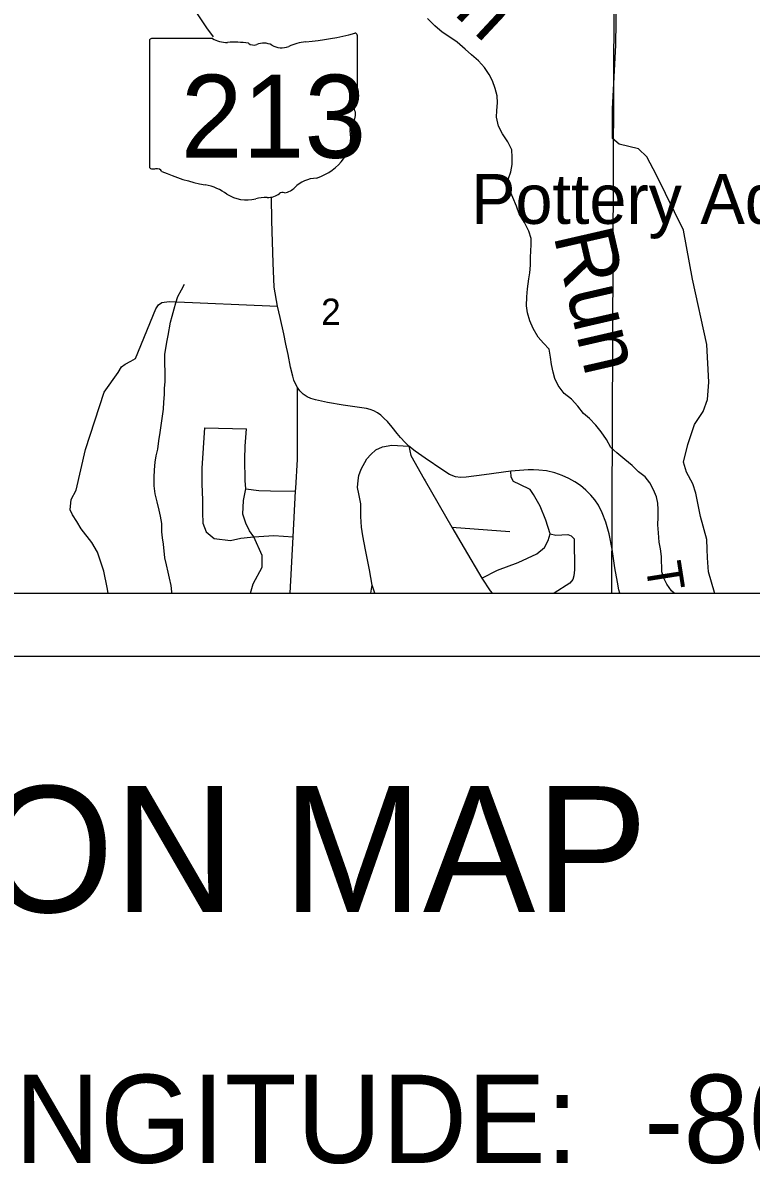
# Model space of a CAD drawing. Extents: x 0 to 34, y 0 to 22.
# Drawn here: x 5.456 to 6.612, y 13.194 to 15.005 of the extents above; entities that cross this region are included whole.
import ezdxf

# ---------------------------------------------------------------- set-up
doc = ezdxf.new("R2010")
doc.units = 0
for name, color, linetype in [('Default', 7, 'Continuous'), ('GM_X_Minor_River', 7, 'Continuous'), ('GM_X_Minor_River_Text', 7, 'Continuous'), ('GM_X_Section_Text', 7, 'Continuous'), ('GM_X_State_Location', 7, 'Continuous'), ('GM_X_State_Route', 7, 'Continuous'), ('GM_X_State_Shield', 7, 'Continuous'), ('GM_X_Township_Road', 7, 'Continuous'), ('GM_X_Township_Road_Text', 7, 'Continuous'), ('GM_X_Unincorporated_Text', 7, 'Continuous'), ('SH_Cut_Line', 7, 'Continuous'), ('SH_Data', 7, 'Continuous'), ('SH_Text', 7, 'Continuous')]:
    doc.layers.add(name, color=color, linetype=linetype)

msp = doc.modelspace()

# ---------------------------------------------------------------- linework, layer by layer
at = {"layer": 'Default'}
for p, q in [((6.3909, 14.1), (6.3944, 15.0386)), ((2.1, 14.1), (6.7017, 14.1)), ((5.3878, 14.1), (6.3909, 14.1))]:
    msp.add_line(p, q, dxfattribs=at)
at = {"layer": 'GM_X_Minor_River'}
for p, q in [((6.11, 15.0003), (6.0986, 15.0121)), ((6.1218, 14.9901), (6.11, 15.0003)), ((6.1338, 14.9821), (6.1218, 14.9901)), ((6.1455, 14.9744), (6.1338, 14.9821)), ((6.1583, 14.9634), (6.1455, 14.9744)), ((6.1681, 14.9542), (6.1583, 14.9634)), ((6.1791, 14.9447), (6.1681, 14.9542)), ((6.1889, 14.934), (6.1791, 14.9447)), ((6.1965, 14.9232), (6.1889, 14.934)), ((6.2014, 14.9127), (6.1965, 14.9232)), ((6.2059, 14.9007), (6.2014, 14.9127)), ((6.209, 14.889), (6.2059, 14.9007)), ((6.2093, 14.8783), (6.209, 14.889)), ((6.2082, 14.8658), (6.2093, 14.8783)), ((6.2077, 14.8555), (6.2082, 14.8658)), ((6.2109, 14.8408), (6.2077, 14.8555)), ((6.2173, 14.8288), (6.2109, 14.8408)), ((6.2257, 14.8161), (6.2173, 14.8288)), ((6.2322, 14.8034), (6.2257, 14.8161)), ((6.2329, 14.792), (6.2322, 14.8034)), ((6.2306, 14.7688), (6.2325, 14.7802)), ((6.2325, 14.7802), (6.2329, 14.792)), ((6.2268, 14.758), (6.2306, 14.7688)), ((6.2248, 14.7484), (6.2268, 14.758)), ((6.2338, 14.7278), (6.2248, 14.7484)), ((6.2395, 14.7143), (6.2338, 14.7278)), ((6.2437, 14.7019), (6.2395, 14.7143)), ((6.2521, 14.6884), (6.2437, 14.7019)), ((6.2594, 14.6746), (6.2521, 14.6884)), ((6.2628, 14.6629), (6.2594, 14.6746)), ((6.2623, 14.6428), (6.2631, 14.6534)), ((6.2631, 14.6534), (6.2628, 14.6629)), ((6.2619, 14.6329), (6.2623, 14.6428)), ((6.2607, 14.6085), (6.2619, 14.6207)), ((6.2619, 14.6207), (6.2619, 14.6329)), ((6.257, 14.5829), (6.2591, 14.5986)), ((6.2591, 14.5986), (6.2607, 14.6085)), ((5.7023, 14.5708), (5.708, 14.5813)), ((5.708, 14.5813), (5.7131, 14.5902)), ((6.2562, 14.5703), (6.257, 14.5829)), ((5.6992, 14.5608), (5.7023, 14.5708)), ((6.2555, 14.5559), (6.2562, 14.5703)), ((5.6934, 14.5397), (5.6964, 14.5513)), ((5.6964, 14.5513), (5.6992, 14.5608)), ((6.257, 14.5449), (6.2555, 14.5559)), ((6.2608, 14.5321), (6.257, 14.5449)), ((5.6867, 14.5091), (5.6906, 14.5298)), ((5.6906, 14.5298), (5.6934, 14.5397)), ((6.2662, 14.5201), (6.2608, 14.5321)), ((5.6848, 14.4984), (5.6867, 14.5091)), ((6.2742, 14.5063), (6.2662, 14.5201)), ((5.6816, 14.4785), (5.6848, 14.4984)), ((6.2825, 14.4966), (6.2742, 14.5063)), ((6.2912, 14.487), (6.2825, 14.4966)), ((5.6815, 14.469), (5.6816, 14.4785)), ((6.2934, 14.4745), (6.2912, 14.487)), ((6.295, 14.4628), (6.2934, 14.4745)), ((5.6822, 14.4462), (5.6815, 14.469)), ((6.298, 14.4507), (6.295, 14.4628)), ((5.6814, 14.4249), (5.6822, 14.4356)), ((5.6822, 14.4356), (5.6822, 14.4462)), ((6.3006, 14.4406), (6.298, 14.4507)), ((6.3055, 14.4293), (6.3006, 14.4406)), ((5.6809, 14.4154), (5.6814, 14.4249)), ((6.315, 14.4167), (6.3055, 14.4293)), ((6.3267, 14.4079), (6.315, 14.4167)), ((5.6794, 14.3918), (5.6802, 14.4032)), ((5.6802, 14.4032), (5.6809, 14.4154)), ((6.3369, 14.3968), (6.3267, 14.4079)), ((5.676, 14.3658), (5.6782, 14.3807)), ((5.6782, 14.3807), (5.6794, 14.3918)), ((6.3457, 14.3853), (6.3369, 14.3968)), ((6.3554, 14.3769), (6.3457, 14.3853)), ((5.6745, 14.3548), (5.676, 14.3658)), ((6.3657, 14.3666), (6.3554, 14.3769)), ((6.374, 14.3562), (6.3657, 14.3666)), ((5.6722, 14.3418), (5.6745, 14.3548)), ((6.3823, 14.3439), (6.374, 14.3562)), ((6.3892, 14.3312), (6.3823, 14.3439)), ((5.668, 14.3181), (5.6704, 14.3284)), ((5.6704, 14.3284), (5.6722, 14.3418)), ((6.399, 14.3227), (6.3892, 14.3312)), ((5.6653, 14.2955), (5.6664, 14.3077)), ((5.6664, 14.3077), (5.668, 14.3181)), ((6.4115, 14.3121), (6.399, 14.3227)), ((6.4232, 14.3026), (6.4115, 14.3121)), ((5.6649, 14.2837), (5.6653, 14.2955)), ((6.4334, 14.2926), (6.4232, 14.3026)), ((6.4435, 14.2846), (6.4334, 14.2926)), ((5.665, 14.2704), (5.6649, 14.2837)), ((6.4514, 14.275), (6.4435, 14.2846)), ((6.4567, 14.2641), (6.4514, 14.275)), ((5.6661, 14.2575), (5.665, 14.2704)), ((5.6695, 14.2451), (5.6661, 14.2575)), ((6.4616, 14.2528), (6.4567, 14.2641)), ((5.6726, 14.2319), (5.6695, 14.2451)), ((6.4638, 14.243), (6.4616, 14.2528)), ((6.4645, 14.2328), (6.4638, 14.243)), ((5.6748, 14.2221), (5.6726, 14.2319)), ((5.6767, 14.2103), (5.6748, 14.2221)), ((6.4641, 14.2084), (6.4645, 14.2206)), ((6.4645, 14.2206), (6.4645, 14.2328)), ((5.6771, 14.1974), (5.6767, 14.2103)), ((6.4649, 14.1955), (6.4641, 14.2084)), ((5.6782, 14.188), (5.6771, 14.1974)), ((5.6796, 14.1777), (5.6782, 14.188)), ((6.4661, 14.1811), (6.4649, 14.1955)), ((6.468, 14.1705), (6.4661, 14.1811)), ((5.6819, 14.1558), (5.6796, 14.1777)), ((6.4695, 14.1584), (6.468, 14.1705)), ((5.6845, 14.1452), (5.6819, 14.1558)), ((5.6871, 14.1335), (5.6845, 14.1452)), ((6.4703, 14.1337), (6.4695, 14.1584)), ((5.6893, 14.1237), (5.6871, 14.1335)), ((6.4736, 14.124), (6.4703, 14.1337)), ((5.6916, 14.1123), (5.6893, 14.1237)), ((5.6927, 14.1021), (5.6916, 14.1123)), ((6.4781, 14.1142), (6.4736, 14.124)), ((6.4853, 14.1038), (6.4781, 14.1142)), ((5.6929, 14.1), (5.6927, 14.1021)), ((6.4895, 14.1), (6.4853, 14.1038))]:
    msp.add_line(p, q, dxfattribs=at)
at = {"layer": 'GM_X_State_Route'}
for p, q in [((5.7484, 14.9968), (5.7323, 15.021)), ((5.7587, 14.9827), (5.7484, 14.9968)), ((5.8516, 14.6909), (5.8509, 14.7284)), ((5.8537, 14.6242), (5.8516, 14.6909)), ((5.8552, 14.5856), (5.8537, 14.6242)), ((5.8604, 14.5555), (5.8552, 14.5856)), ((5.8645, 14.5376), (5.8604, 14.5555)), ((5.8704, 14.5116), (5.8645, 14.5376)), ((5.8739, 14.4953), (5.8704, 14.5116)), ((5.8773, 14.4788), (5.8739, 14.4953)), ((5.8813, 14.4587), (5.8773, 14.4788)), ((5.8846, 14.4443), (5.8813, 14.4587)), ((5.8865, 14.438), (5.8846, 14.4443)), ((5.889, 14.4321), (5.8865, 14.438)), ((5.8923, 14.4262), (5.889, 14.4321)), ((5.8961, 14.421), (5.8923, 14.4262)), ((5.901, 14.4159), (5.8961, 14.421)), ((5.9074, 14.4116), (5.901, 14.4159)), ((5.9135, 14.4087), (5.9074, 14.4116)), ((5.9207, 14.4065), (5.9135, 14.4087)), ((5.9398, 14.4026), (5.9207, 14.4065)), ((5.9646, 14.3983), (5.9398, 14.4026)), ((6.0017, 14.3931), (5.9646, 14.3983)), ((6.0076, 14.3916), (6.0017, 14.3931)), ((6.0134, 14.3894), (6.0076, 14.3916)), ((6.0189, 14.3862), (6.0134, 14.3894)), ((6.0244, 14.3823), (6.0189, 14.3862)), ((6.0299, 14.3774), (6.0244, 14.3823)), ((6.0349, 14.3722), (6.0299, 14.3774)), ((6.0425, 14.3635), (6.0349, 14.3722)), ((6.0503, 14.3536), (6.0425, 14.3635)), ((6.0556, 14.347), (6.0503, 14.3536)), ((6.0629, 14.3389), (6.0556, 14.347)), ((6.069, 14.3331), (6.0629, 14.3389)), ((6.0789, 14.3253), (6.069, 14.3331)), ((6.0946, 14.3142), (6.0789, 14.3253)), ((6.1225, 14.295), (6.0946, 14.3142)), ((6.1334, 14.2883), (6.1225, 14.295)), ((6.2306, 14.2935), (6.1882, 14.288)), ((6.2582, 14.2958), (6.2306, 14.2935)), ((6.2667, 14.2958), (6.2582, 14.2958)), ((6.275, 14.2952), (6.2667, 14.2958)), ((6.2874, 14.2939), (6.275, 14.2952)), ((6.3003, 14.2907), (6.2874, 14.2939)), ((6.3118, 14.2867), (6.3003, 14.2907)), ((6.1426, 14.2847), (6.1334, 14.2883)), ((6.1508, 14.2837), (6.1426, 14.2847)), ((6.1595, 14.2838), (6.1508, 14.2837)), ((6.1882, 14.288), (6.1595, 14.2838)), ((6.3229, 14.2817), (6.3118, 14.2867)), ((6.3319, 14.2769), (6.3229, 14.2817)), ((6.3411, 14.271), (6.3319, 14.2769)), ((6.3498, 14.2635), (6.3411, 14.271)), ((6.3578, 14.2555), (6.3498, 14.2635)), ((6.3638, 14.2481), (6.3578, 14.2555)), ((6.3695, 14.2395), (6.3638, 14.2481)), ((6.3756, 14.2276), (6.3695, 14.2395)), ((6.3815, 14.2129), (6.3756, 14.2276)), ((6.3866, 14.1942), (6.3815, 14.2129)), ((6.3913, 14.1696), (6.3866, 14.1942)), ((6.3955, 14.1402), (6.3913, 14.1696)), ((6.3996, 14.1172), (6.3955, 14.1402)), ((6.4021, 14.1051), (6.3996, 14.1172)), ((6.4038, 14.1), (6.4021, 14.1051))]:
    msp.add_line(p, q, dxfattribs=at)
at = {"layer": 'GM_X_State_Shield'}
for p, q in [((5.7573, 14.9802), (5.6607, 14.9802)), ((5.9871, 14.8805), (5.9871, 14.9852)), ((5.6575, 14.9768), (5.6575, 14.7766)), ((5.987, 14.8805), (5.9871, 14.8805))]:
    msp.add_line(p, q, dxfattribs=at)
for centre, major_axis, start_param, end_param in [((5.6613, 14.9772), (0.00382, 0), 1.712693, 3.28349), ((5.7802, 15.0034), (0.037, 0), 4.042888, 4.731795), ((5.8697, 15.253), (0.3495, 0), 4.814394, 5.042369), ((5.9834, 14.9856), (0.00367, 0), 6.141152, 7.989035), ((5.7925, 14.8679), (0.133, 0), 1.404758, 1.657858), ((5.8227, 14.9782), (0.0107, 0), 3.836095, 5.185415), ((5.8384, 14.9551), (0.0222, 0), 0.950623, 2.079405), ((5.8671, 14.9868), (0.0267, 0), 4.081561, 5.145723), ((5.9143, 14.9191), (0.0703, 0), 1.699011, 2.107814), ((5.9862, 14.8728), (0.00568, 0), 1.883978, 3.671073), ((5.9501, 14.8596), (0.0341, 0), 5.934695, 6.695948), ((5.9832, 14.8801), (0.00393, 0), 5.05454, 6.418171), ((5.8892, 14.8234), (0.0874, 0), 5.101752, 6.440018), ((6.0002, 14.8367), (0.0248, 0), 2.387724, 3.262537), ((5.6613, 14.7762), (0.00385, 0), 3.00124, 4.508301), ((5.6619, 14.7967), (0.0294, 0), 4.665946, 4.897461), ((5.6679, 14.7651), (0.0106, 0), 0.519207, 1.627899), ((5.8017, 14.9449), (0.2524, 0), 4.195997, 4.488961), ((5.7265, 14.6867), (0.079, 0), 0.823519, 1.323587), ((5.8654, 14.7573), (0.0282, 0), 4.937069, 5.64225), ((5.9261, 14.7205), (0.0479, 0), 1.647645, 2.488434), ((5.8119, 14.7641), (0.0501, 0), 4.026481, 4.996735), ((5.8408, 14.6949), (0.0412, 0), 1.495662, 1.94098), ((5.8445, 14.7491), (0.0267, 0), 4.691044, 5.507374), ((5.8687, 14.7297), (0.00752, 0), 1.147584, 2.315152)]:
    msp.add_ellipse(centre, major_axis=major_axis, ratio=0.8, start_param=start_param, end_param=end_param, dxfattribs=at)
at = {"layer": 'GM_X_Township_Road'}
for p, q in [((6.397, 14.9697), (6.4001, 15.1741)), ((6.3917, 14.8684), (6.397, 14.9697)), ((6.3921, 14.8215), (6.3917, 14.8684)), ((6.4023, 14.8125), (6.3921, 14.8215)), ((6.4334, 14.8052), (6.4023, 14.8125)), ((6.4464, 14.7925), (6.4334, 14.8052)), ((6.4619, 14.7635), (6.4464, 14.7925)), ((6.5048, 14.6762), (6.4619, 14.7635)), ((6.5189, 14.5984), (6.5048, 14.6762)), ((6.5416, 14.4943), (6.5189, 14.5984)), ((5.6714, 14.5573), (5.6768, 14.5612)), ((5.6768, 14.5612), (5.6888, 14.563)), ((5.6888, 14.563), (5.8604, 14.5555)), ((5.635, 14.4726), (5.6673, 14.5509)), ((5.6673, 14.5509), (5.6714, 14.5573)), ((6.5449, 14.435), (6.5416, 14.4943)), ((5.6276, 14.4683), (5.635, 14.4726)), ((5.6074, 14.4502), (5.6129, 14.4591)), ((5.6129, 14.4591), (5.6189, 14.4634)), ((5.6189, 14.4634), (5.6276, 14.4683)), ((5.5853, 14.4191), (5.6074, 14.4502)), ((6.5425, 14.4071), (6.5449, 14.435)), ((5.5559, 14.3282), (5.5853, 14.4191)), ((5.892, 14.3121), (5.8923, 14.4262)), ((6.5356, 14.3885), (6.5425, 14.4071)), ((6.5222, 14.3676), (6.5356, 14.3885)), ((5.7444, 14.3625), (5.7404, 14.2984)), ((5.7444, 14.3625), (5.8113, 14.3609)), ((6.5112, 14.3359), (6.5222, 14.3676)), ((5.8089, 14.333), (5.8113, 14.3609)), ((5.541, 14.2632), (5.5559, 14.3282)), ((5.8085, 14.3125), (5.8089, 14.333)), ((6.0085, 14.3201), (6.0163, 14.3276)), ((6.0163, 14.3276), (6.0272, 14.3324)), ((6.0272, 14.3324), (6.042, 14.3347)), ((6.042, 14.3347), (6.069, 14.3331)), ((6.069, 14.3331), (6.0719, 14.3182)), ((6.5046, 14.3081), (6.5112, 14.3359)), ((5.8093, 14.2787), (5.8085, 14.3125)), ((5.8895, 14.2664), (5.892, 14.3121)), ((5.9931, 14.2969), (6.0021, 14.3129)), ((6.0021, 14.3129), (6.0085, 14.3201)), ((6.0719, 14.3182), (6.0932, 14.2807)), ((6.5091, 14.2922), (6.5046, 14.3081)), ((5.7404, 14.2984), (5.7404, 14.2736)), ((5.9892, 14.2869), (5.9931, 14.2969)), ((6.231, 14.2838), (6.2306, 14.2935)), ((6.5194, 14.2737), (6.5091, 14.2922)), ((5.7404, 14.2736), (5.7412, 14.2476)), ((5.8101, 14.2657), (5.8093, 14.2787)), ((5.9876, 14.2677), (5.9883, 14.2786)), ((5.9883, 14.2786), (5.9892, 14.2869)), ((6.0932, 14.2807), (6.0946, 14.2782)), ((6.0946, 14.2782), (6.1372, 14.2049)), ((6.2351, 14.277), (6.231, 14.2838)), ((6.2448, 14.2722), (6.2351, 14.277)), ((6.2613, 14.2646), (6.2448, 14.2722)), ((6.5242, 14.2589), (6.5194, 14.2737)), ((5.533, 14.2488), (5.541, 14.2632)), ((5.8066, 14.2472), (5.8101, 14.2657)), ((5.8101, 14.2657), (5.8306, 14.2629)), ((5.8306, 14.2629), (5.8491, 14.2621)), ((5.8491, 14.2621), (5.8892, 14.2618)), ((5.8853, 14.1893), (5.8892, 14.2618)), ((5.8892, 14.2618), (5.8895, 14.2664)), ((5.9896, 14.2578), (5.9876, 14.2677)), ((5.9924, 14.2417), (5.9896, 14.2578)), ((6.2668, 14.2568), (6.2613, 14.2646)), ((6.2774, 14.2381), (6.2668, 14.2568)), ((6.5315, 14.2217), (6.5242, 14.2589)), ((5.5316, 14.2321), (5.533, 14.2488)), ((5.7412, 14.2476), (5.7412, 14.2279)), ((5.8054, 14.2252), (5.8066, 14.2472)), ((5.9928, 14.2215), (5.9924, 14.2417)), ((6.286, 14.216), (6.2774, 14.2381)), ((5.5354, 14.2241), (5.5316, 14.2321)), ((5.5421, 14.2136), (5.5354, 14.2241)), ((5.7412, 14.2279), (5.742, 14.211)), ((5.8101, 14.211), (5.8054, 14.2252)), ((5.9936, 14.2047), (5.9928, 14.2215)), ((6.5414, 14.1853), (6.5315, 14.2217)), ((5.549, 14.2021), (5.5421, 14.2136)), ((5.5659, 14.1802), (5.549, 14.2021)), ((5.742, 14.211), (5.7471, 14.1972)), ((5.8158, 14.1989), (5.8101, 14.211)), ((5.9958, 14.1912), (5.9936, 14.2047)), ((6.1372, 14.2049), (6.229, 14.1978)), ((6.1372, 14.2049), (6.1565, 14.1713)), ((6.2928, 14.1939), (6.286, 14.216)), ((5.7471, 14.1972), (5.7601, 14.1866)), ((5.7601, 14.1866), (5.7859, 14.1835)), ((5.7859, 14.1835), (5.8022, 14.187)), ((5.8022, 14.187), (5.8178, 14.1888)), ((5.8227, 14.1893), (5.8158, 14.1989)), ((5.8178, 14.1888), (5.8227, 14.1893)), ((5.8227, 14.1893), (5.8546, 14.1913)), ((5.8361, 14.1598), (5.8227, 14.1893)), ((5.8546, 14.1913), (5.8853, 14.1893)), ((5.8805, 14.1), (5.8853, 14.1893)), ((6.0001, 14.1685), (5.9958, 14.1912)), ((6.2839, 14.1723), (6.2897, 14.1837)), ((6.2897, 14.1837), (6.2928, 14.1939)), ((6.2928, 14.1939), (6.3019, 14.1921)), ((6.3019, 14.1921), (6.3208, 14.1932)), ((6.3208, 14.1932), (6.3264, 14.1907)), ((6.3264, 14.1907), (6.3309, 14.1864)), ((6.3309, 14.1864), (6.3317, 14.1369)), ((6.5422, 14.1698), (6.5414, 14.1853)), ((5.5747, 14.165), (5.5659, 14.1802)), ((5.5848, 14.1347), (5.5747, 14.165)), ((6.0062, 14.1372), (6.0001, 14.1685)), ((6.1565, 14.1713), (6.1848, 14.1237)), ((6.2718, 14.1622), (6.2839, 14.1723)), ((6.5429, 14.1563), (6.5422, 14.1698)), ((5.8363, 14.1411), (5.8361, 14.1598)), ((6.2096, 14.1364), (6.2425, 14.1489)), ((6.2425, 14.1489), (6.2718, 14.1622)), ((6.5441, 14.1336), (6.5429, 14.1563)), ((5.5903, 14.109), (5.5848, 14.1347)), ((5.8219, 14.1148), (5.8363, 14.1411)), ((6.0107, 14.1127), (6.0062, 14.1372)), ((6.1848, 14.1237), (6.2096, 14.1364)), ((6.3308, 14.1273), (6.3289, 14.1217)), ((6.3317, 14.1369), (6.3308, 14.1273)), ((6.5536, 14.1008), (6.5441, 14.1336)), ((5.5917, 14.1), (5.5903, 14.109)), ((5.8174, 14.1), (5.8219, 14.1148)), ((6.0086, 14.1), (6.0107, 14.1127)), ((6.0148, 14.1), (6.0107, 14.1127)), ((6.1848, 14.1237), (6.198, 14.1038)), ((6.3243, 14.1158), (6.2993, 14.1)), ((6.3289, 14.1217), (6.3243, 14.1158)), ((6.198, 14.1038), (6.201, 14.1)), ((6.5541, 14.1), (6.5536, 14.1008))]:
    msp.add_line(p, q, dxfattribs=at)
at = {"layer": 'SH_Cut_Line'}
msp.add_line((2.1, 14.1), (6.7017, 14.1), dxfattribs=at)
at = {"layer": 'SH_Data'}
for p, q in [((2.1, 14.1), (8.9, 14.1)), ((2, 14), (9, 14))]:
    msp.add_line(p, q, dxfattribs=at)

# ---------------------------------------------------------------- texts
at = {"layer": 'GM_X_Minor_River_Text'}
for s, height, rotation, p in [('Rush', 0.0947, 316.972, (5.9737, 15.173)), ('Run', 0.09467, 282.9749, (6.298, 14.668))]:
    msp.add_text(s, height=height, rotation=rotation, dxfattribs=at).set_placement(p)
at = {"layer": 'GM_X_Section_Text'}
msp.add_text('2', height=0.0419, rotation=0, dxfattribs=at).set_placement((5.9296, 14.5255))
at = {"layer": 'GM_X_State_Location'}
for s in ['s', 'r']:
    msp.add_text(s, height=0.000189, dxfattribs=at).set_placement((5.8186, 14.8634))
msp.add_text('213', height=0.000189, rotation=0, dxfattribs=at).set_placement((5.7517, 14.8496))
at = {"layer": 'GM_X_State_Shield'}
msp.add_text('213', height=0.13184, dxfattribs=at).set_placement((5.707, 14.7908))
at = {"layer": 'GM_X_Township_Road_Text'}
msp.add_text('T', height=0.0568, rotation=278.9762, dxfattribs=at).set_placement((6.4438, 14.1456))
at = {"layer": 'GM_X_Unincorporated_Text'}
msp.add_text('Pottery Addition', height=0.078977, rotation=0, dxfattribs=at).set_placement((6.1675, 14.686))
at = {"layer": 'SH_Text'}
for s, height, p in [('LOCATION MAP', 0.2, (4.4269, 13.5938)), ('LATITUDE:  40°26\'30"     LONGITUDE:  -80°39\'45"', 0.14, (3.071, 13.1959))]:
    msp.add_text(s, height=height, dxfattribs=at).set_placement(p)

doc.saveas('drawing.dxf')
